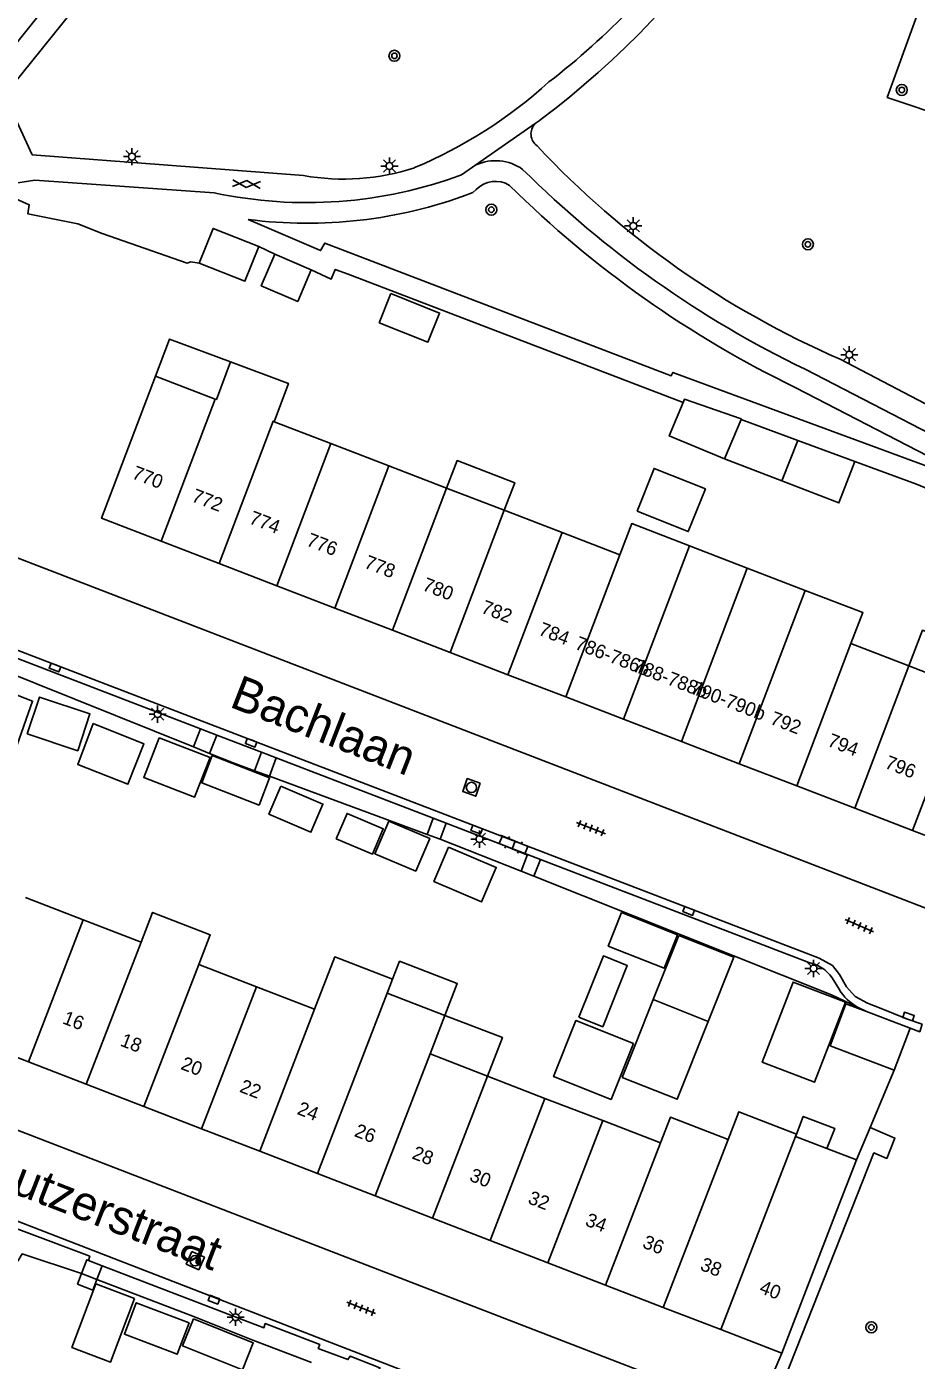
# Model space of a CAD drawing. Extents: x 132999 to 136000, y 398499 to 400501.
# Drawn here: x 134407.7 to 134472.4, y 398964.6 to 399061.5 of the extents above; entities that cross this region are included whole.
import ezdxf

# ---------------------------------------------------------------- set-up
doc = ezdxf.new("R2010")
doc.units = 0
for name, color, linetype in [('gg-afsc-erfafscheiding', 7, 'Continuous'), ('gg-afsc-muur', 7, 'Continuous'), ('gg-anno-huisnummerreeks BGT', 7, 'Continuous'), ('gg-anno-openbare ruimte label', 7, 'Continuous'), ('gg-bbg-bijgebouw', 7, 'Continuous'), ('gg-bbg-gedigitaliseerde bebouwing', 7, 'Continuous'), ('gg-bbg-gedigitaliseerde bijgebouw', 7, 'Continuous'), ('gg-bbg-hoofdgebouw', 7, 'Continuous'), ('gg-bbg-luifel en loopbrug', 7, 'Continuous'), ('gg-bbg-tussenscheiding', 7, 'Continuous'), ('gg-knt-verharding', 7, 'Continuous'), ('gt-grn-groengrens', 7, 'Continuous'), ('gt-grn-vlakafsluiter', 7, 'Continuous'), ('gt-grn-weggrens', 7, 'Continuous'), ('gt-symb-boom', 7, 'Continuous'), ('gt-symb-gesloten verharding', 7, 'Continuous'), ('gt-symb-klinker verharding', 7, 'Continuous'), ('gt-symb-kolk', 7, 'Continuous'), ('gt-symb-lichtmast', 7, 'Continuous'), ('gt-symb-rioolschacht', 7, 'Continuous'), ('gt-symb-tegel verharding', 7, 'Continuous')]:
    doc.layers.add(name, color=color, linetype=linetype)

# ---------------------------------------------------------------- blocks, each defined once
blk = doc.blocks.new('gt0-GESVH1')
at = {"layer": 'gt-symb-gesloten verharding'}
for p, q in [((-0.992, -0.261), (0.008, 0.239)), ((0.008, -0.261), (-0.992, 0.239)), ((0.008, 0.239), (1.008, -0.261)), ((1.008, 0.239), (0.008, -0.261))]:
    blk.add_line(p, q, dxfattribs=at)
blk = doc.blocks.new('gt0-LMAST')
at = {"layer": 'gt-symb-lichtmast'}
for p, q in [((-0.182, 0.173), (-0.447, 0.438)), ((-0.005, 0.246), (-0.005, 0.621)), ((0.172, 0.173), (0.437, 0.438)), ((-0.255, -0.004), (-0.63, -0.004)), ((-0.182, -0.181), (-0.447, -0.446)), ((-0.005, -0.254), (-0.005, -0.629)), ((0.437, -0.446), (0.172, -0.181)), ((0.245, -0.004), (0.62, -0.004))]:
    blk.add_line(p, q, dxfattribs=at)
blk.add_circle((-0.005, -0.004), 0.25, dxfattribs=at)
blk = doc.blocks.new('gt0-BOOM')
at = {"layer": 'gt-symb-boom'}
for radius in [0.4, 0.2]:
    blk.add_circle((0, 0), radius, dxfattribs=at)
blk = doc.blocks.new('gt0-KOLK')
at = {"layer": 'gt-symb-kolk'}
blk.add_lwpolyline([(0, 0), (0.375, 0), (0.375, 0.4), (-0.375, 0.4), (-0.375, 0), (0, 0)], dxfattribs=at)
blk = doc.blocks.new('gt0-RS')
at = {"layer": 'gt-symb-rioolschacht'}
blk.add_lwpolyline([(-0.5, -0.5), (0.5, -0.5), (0.5, 0.5), (-0.5, 0.5)], close=True, dxfattribs=at)
blk.add_circle((0, 0), 0.375, dxfattribs=at)
blk = doc.blocks.new('gt0-KL1')
at = {"layer": 'gt-symb-klinker verharding'}
for p, q in [((-1.15, 0.3), (1.15, 0.3)), ((-1, -0.3), (-1, 0.3)), ((-0.5, 0.3), (-0.5, 0.45)), ((0, -0.3), (0, 0.3)), ((0.5, 0.3), (0.5, 0.45)), ((1, -0.3), (1, 0.3)), ((-1.15, -0.3), (1.15, -0.3)), ((-0.5, -0.45), (-0.5, -0.3)), ((0.5, -0.45), (0.5, -0.3))]:
    blk.add_line(p, q, dxfattribs=at)
blk = doc.blocks.new('gt0-TEG1')
at = {"layer": 'gt-symb-tegel verharding'}
for p, q in [((-1.125, 0), (1.125, 0)), ((-0.9, -0.25), (-0.9, 0.25)), ((-0.45, -0.25), (-0.45, 0.25)), ((0, -0.25), (0, 0.25)), ((0.45, -0.25), (0.45, 0.25)), ((0.9, -0.25), (0.9, 0.25))]:
    blk.add_line(p, q, dxfattribs=at)

msp = doc.modelspace()

# ---------------------------------------------------------------- linework, layer by layer
at = {"layer": 'gg-afsc-erfafscheiding'}
for p, q in [((134406.46, 399023.137), (134411.423, 399021.222)), ((134419.832, 399009.154), (134404.31, 399015.39)), ((134420.998, 399008.686), (134419.832, 399009.154)), ((134425.36, 399007.022), (134424.287, 399007.417)), ((134436.83, 399002.796), (134425.36, 399007.022)), ((134437.775, 399002.448), (134436.83, 399002.796)), ((134437.775, 399002.448), (134443.657, 399000.128)), ((134443.657, 399000.128), (134444.587, 398999.757)), ((134469.032, 398981.481), (134470.799, 398985.653)), ((134468.038, 398979.133), (134469.032, 398981.481)), ((134411.704, 398970.859), (134412.134, 398970.689)), ((134412.134, 398970.689), (134412.827, 398970.424)), ((134412.827, 398970.424), (134419.924, 398967.716)), ((134462.61, 398965.08), (134460.7, 398960.57))]:
    msp.add_line(p, q, dxfattribs=at)
for points in [[(134467.921, 399029.91), (134472.408, 399028.252), (134490.606, 399020.656)], [(134424.287, 399007.417), (134422.718, 399007.995), (134420.998, 399008.686)], [(134444.587, 398999.757), (134466.239, 398991.129), (134468.124, 398990.227)]]:
    msp.add_lwpolyline(points, dxfattribs=at)
at = {"layer": 'gg-afsc-muur'}
msp.add_line((134424.597, 399045.554), (134425.751, 399044.979), dxfattribs=at)
for points in [[(134420.248, 399044.324), (134419.657, 399044.429), (134419.393, 399044.341), (134413.201, 399046.499), (134411.429, 399047.204), (134407.788, 399047.923), (134407.899, 399048.584), (134406.668, 399049.129)], [(134428.406, 399043.847), (134429.861, 399043.176), (134430.155, 399043.879), (134431.085, 399043.541), (134455.438, 399034.195)], [(134419.924, 398967.716), (134424.151, 398966.034), (134428.422, 398964.39)]]:
    msp.add_lwpolyline(points, dxfattribs=at)
at = {"layer": 'gg-bbg-bijgebouw'}
msp.add_line((134425.751, 399044.979), (134428.406, 399043.847), dxfattribs=at)
for points in [[(134420.248, 399044.324), (134421.267, 399046.861), (134424.597, 399045.554)], [(134424.597, 399045.554), (134423.578, 399043.018), (134420.248, 399044.324)], [(134428.406, 399043.847), (134427.429, 399041.557), (134424.774, 399042.689), (134425.751, 399044.979)], [(134455.438, 399034.195), (134455.542, 399034.444), (134459.669, 399033.004), (134459.653, 399032.965)], [(134458.463, 399030.101), (134454.433, 399031.775), (134455.438, 399034.195)]]:
    msp.add_lwpolyline(points, dxfattribs=at)
at = {"layer": 'gg-bbg-gedigitaliseerde bebouwing'}
for p, q in [((134455.897, 399023.783), (134460.109, 399022.163)), ((134460.109, 399022.163), (134464.318, 399020.543)), ((134407.624, 398998.21), (134411.83, 398996.584)), ((134411.83, 398996.584), (134416.028, 398994.961)), ((134420.225, 398993.338), (134424.422, 398991.716)), ((134424.422, 398991.716), (134428.646, 398990.083)), ((134434.312, 398992.26), (134433.924, 398991.257)), ((134438.122, 398989.635), (134433.924, 398991.257)), ((134437.041, 398986.837), (134438.122, 398989.635)), ((134437.041, 398986.837), (134441.22, 398985.222)), ((134441.22, 398985.222), (134445.399, 398983.606)), ((134445.399, 398983.606), (134449.597, 398981.983)), ((134449.597, 398981.983), (134453.794, 398980.361)), ((134463.617, 398980.841), (134463.681, 398981.006)), ((134465.902, 398979.958), (134463.617, 398980.841)), ((134468.038, 398979.133), (134465.902, 398979.958))]:
    msp.add_line(p, q, dxfattribs=at)
for points in [[(134450.837, 399023.135), (134451.707, 399025.395), (134455.897, 399023.783)], [(134464.318, 399020.543), (134468.517, 399018.928), (134467.647, 399016.667)], [(134420.225, 398993.338), (134421.06, 398995.503), (134416.864, 398997.124), (134416.028, 398994.961)], [(134428.646, 398990.083), (134430.115, 398993.883), (134434.312, 398992.26)], [(134458.714, 398980.612), (134454.516, 398982.233), (134453.794, 398980.361)], [(134458.714, 398980.612), (134459.491, 398982.625), (134463.681, 398981.006)]]:
    msp.add_lwpolyline(points, dxfattribs=at)
at = {"layer": 'gg-bbg-gedigitaliseerde bijgebouw'}
for p, q in [((134433.352, 399040.006), (134434.197, 399042.119)), ((134459.653, 399032.965), (134463.787, 399031.437)), ((134463.787, 399031.437), (134467.921, 399029.91)), ((134458.463, 399030.101), (134462.614, 399028.504)), ((134453.275, 398990.793), (134455.131, 398995.452)), ((134457.266, 398989.203), (134453.275, 398990.793)), ((134467.282, 398990.482), (134468.775, 398989.915)), ((134468.775, 398989.915), (134471.959, 398988.705)), ((134471.959, 398988.705), (134470.799, 398985.653))]:
    msp.add_line(p, q, dxfattribs=at)
for points in [[(134434.197, 399042.119), (134437.738, 399040.704), (134436.893, 399038.591), (134433.352, 399040.006)], [(134462.614, 399028.504), (134466.766, 399026.906), (134467.921, 399029.91)], [(134417.346, 399009.826), (134421.044, 399008.387), (134419.922, 399005.505), (134416.224, 399006.944), (134417.346, 399009.826)], [(134421.213, 399008.536), (134425.381, 399006.914), (134424.61, 399004.931), (134420.441, 399006.553), (134421.213, 399008.536)], [(134426.198, 399006.31), (134429.252, 399005.006), (134428.376, 399002.954), (134425.322, 399004.258), (134426.198, 399006.31)], [(134430.222, 399002.479), (134431.011, 399004.326), (134433.64, 399003.204), (134432.851, 399001.357), (134430.222, 399002.479)], [(134434.054, 399003.768), (134433.04, 399001.394), (134436.003, 399000.129), (134437.017, 399002.504), (134434.054, 399003.768)], [(134438.395, 399001.872), (134437.327, 398999.37), (134440.79, 398997.892), (134441.858, 399000.394), (134438.395, 399001.872)], [(134450.972, 398997.109), (134455.041, 398995.488), (134454.074, 398993.061), (134450.005, 398994.682), (134450.972, 398997.109)], [(134455.131, 398995.452), (134459.122, 398993.862), (134457.266, 398989.203)], [(134467.252, 398990.589), (134465.005, 398984.775), (134461.194, 398986.247), (134463.441, 398992.062), (134467.252, 398990.589)], [(134470.799, 398985.653), (134466.122, 398987.43), (134467.282, 398990.482)], [(134415.566, 398969.059), (134413.815, 398964.431), (134410.999, 398965.497), (134412.749, 398970.124), (134415.566, 398969.059)], [(134419.529, 398967.287), (134415.682, 398968.742), (134414.817, 398966.453), (134418.664, 398964.998), (134419.529, 398967.287)]]:
    msp.add_lwpolyline(points, dxfattribs=at)
at = {"layer": 'gg-bbg-hoofdgebouw'}
for p, q in [((134426.686, 399035.615), (134422.529, 399037.166)), ((134421.419, 399034.455), (134417.091, 399036.12)), ((134429.838, 399031.215), (134425.706, 399032.805)), ((134434.037, 399029.599), (134429.838, 399031.215)), ((134438.237, 399027.983), (134434.037, 399029.599)), ((134442.437, 399026.367), (134438.237, 399027.983)), ((134446.638, 399024.751), (134442.437, 399026.367)), ((134450.837, 399023.135), (134446.638, 399024.751)), ((134417.49, 399024.114), (134421.699, 399022.495)), ((134421.699, 399022.495), (134425.909, 399020.875)), ((134425.909, 399020.875), (134430.108, 399019.259)), ((134430.108, 399019.259), (134434.309, 399017.642)), ((134434.309, 399017.642), (134438.508, 399016.027)), ((134438.508, 399016.027), (134442.709, 399014.41)), ((134471.856, 399015.047), (134467.647, 399016.667)), ((134476.055, 399013.431), (134471.856, 399015.047)), ((134442.709, 399014.41), (134446.908, 399012.794)), ((134446.908, 399012.794), (134451.108, 399011.178)), ((134451.108, 399011.178), (134455.317, 399009.559)), ((134455.317, 399009.559), (134459.527, 399007.939)), ((134459.527, 399007.939), (134463.717, 399006.326)), ((134463.717, 399006.326), (134467.926, 399004.707)), ((134467.926, 399004.707), (134472.126, 399003.091)), ((134472.126, 399003.091), (134476.316, 399001.478)), ((134407.84, 398986.254), (134403.634, 398987.88)), ((134412.037, 398984.631), (134407.84, 398986.254)), ((134416.234, 398983.009), (134412.037, 398984.631)), ((134420.432, 398981.386), (134416.234, 398983.009)), ((134424.656, 398979.753), (134420.432, 398981.386)), ((134428.854, 398978.13), (134424.656, 398979.753)), ((134466.6, 398975.41), (134468.038, 398979.133)), ((134433.051, 398976.507), (134428.854, 398978.13)), ((134437.23, 398974.892), (134433.051, 398976.507)), ((134466.6, 398975.41), (134462.61, 398965.08)), ((134441.409, 398973.276), (134437.23, 398974.892)), ((134445.607, 398971.653), (134441.409, 398973.276)), ((134449.804, 398970.031), (134445.607, 398971.653)), ((134454.001, 398968.408), (134449.804, 398970.031)), ((134458.188, 398966.789), (134454.001, 398968.408)), ((134462.61, 398965.08), (134458.188, 398966.789))]:
    msp.add_line(p, q, dxfattribs=at)
for points in [[(134422.529, 399037.166), (134421.506, 399034.422), (134421.419, 399034.455)], [(134417.091, 399036.12), (134413.161, 399025.78), (134417.49, 399024.114)], [(134425.706, 399032.805), (134426.746, 399035.593), (134426.686, 399035.615)]]:
    msp.add_lwpolyline(points, dxfattribs=at)
at = {"layer": 'gg-bbg-luifel en loopbrug'}
for p, q in [((134453.275, 398990.793), (134451.979, 398987.541)), ((134451.979, 398987.541), (134451.018, 398985.129))]:
    msp.add_line(p, q, dxfattribs=at)
for points in [[(134422.529, 399037.166), (134418.098, 399038.819), (134417.091, 399036.12)], [(134438.237, 399027.983), (134439.006, 399029.982), (134443.206, 399028.366), (134442.437, 399026.367)], [(134452.09, 399026.305), (134453.33, 399029.408), (134457.058, 399027.917), (134455.818, 399024.815), (134452.09, 399026.305)], [(134471.856, 399015.047), (134472.852, 399017.637), (134477.052, 399016.021), (134476.055, 399013.431)], [(134402.644, 399010.99), (134407.019, 399009.3), (134408.148, 399012.495), (134403.844, 399014.158)], [(134407.748, 399010.104), (134411.422, 399008.884), (134412.313, 399011.566), (134408.639, 399012.786), (134407.748, 399010.104)], [(134412.556, 399010.851), (134411.433, 399007.891), (134415.072, 399006.442), (134416.243, 399009.382), (134412.556, 399010.851)], [(134447.872, 398989.503), (134449.649, 398993.962), (134451.382, 398993.272), (134449.605, 398988.812), (134447.872, 398989.503)], [(134434.312, 398992.26), (134434.822, 398993.578), (134439.019, 398991.956), (134438.122, 398989.635)], [(134438.122, 398989.635), (134442.301, 398988.021), (134441.22, 398985.222)], [(134451.835, 398987.598), (134450.211, 398983.523), (134446.03, 398985.189), (134447.654, 398989.264), (134451.835, 398987.598)], [(134451.018, 398985.129), (134455.009, 398983.538), (134457.266, 398989.203)], [(134463.681, 398981.006), (134464.179, 398982.297), (134466.465, 398981.414), (134465.902, 398979.958)], [(134419.835, 398967.572), (134424.19, 398965.839), (134423.407, 398963.871), (134419.053, 398965.604), (134419.835, 398967.572)]]:
    msp.add_lwpolyline(points, dxfattribs=at)
at = {"layer": 'gg-bbg-tussenscheiding'}
for p, q in [((134417.49, 399024.114), (134421.419, 399034.455)), ((134459.653, 399032.965), (134458.463, 399030.101)), ((134462.614, 399028.504), (134463.787, 399031.437)), ((134425.909, 399020.875), (134429.838, 399031.215)), ((134430.108, 399019.259), (134434.037, 399029.599)), ((134434.309, 399017.642), (134438.237, 399027.983)), ((134438.508, 399016.027), (134442.437, 399026.367)), ((134442.709, 399014.41), (134446.638, 399024.751)), ((134451.108, 399011.178), (134455.897, 399023.783)), ((134446.908, 399012.794), (134450.837, 399023.135)), ((134455.317, 399009.559), (134460.109, 399022.163)), ((134459.527, 399007.939), (134464.318, 399020.543)), ((134463.717, 399006.326), (134467.647, 399016.667)), ((134467.926, 399004.707), (134471.856, 399015.047)), ((134472.126, 399003.091), (134476.055, 399013.431)), ((134407.84, 398986.254), (134411.83, 398996.584)), ((134416.028, 398994.961), (134412.037, 398984.631)), ((134416.234, 398983.009), (134420.225, 398993.338)), ((134424.422, 398991.716), (134420.432, 398981.386)), ((134433.924, 398991.257), (134428.854, 398978.13)), ((134428.646, 398990.083), (134424.656, 398979.753)), ((134437.041, 398986.837), (134433.051, 398976.507)), ((134441.22, 398985.222), (134437.23, 398974.892)), ((134441.409, 398973.276), (134445.399, 398983.606)), ((134445.607, 398971.653), (134449.597, 398981.983)), ((134449.804, 398970.031), (134453.794, 398980.361)), ((134454.001, 398968.408), (134458.714, 398980.612)), ((134458.188, 398966.789), (134463.617, 398980.841))]:
    msp.add_line(p, q, dxfattribs=at)
msp.add_lwpolyline([(134421.699, 399022.495), (134425.629, 399032.835), (134425.706, 399032.805)], dxfattribs=at)
at = {"layer": 'gg-knt-verharding'}
for p, q in [((134405.871, 399056.24), (134416.639, 399069.675)), ((134445.037, 399054.728), (134444.68, 399054.479)), ((134408.111, 399052.203), (134427.845, 399050.705)), ((134439.329, 399050.75), (134440.376, 399051.48)), ((134408.297, 399050.372), (134406.611, 399050.09)), ((134408.297, 399050.372), (134421.345, 399049.453)), ((134483.304, 399028.718), (134466.849, 399037.36)), ((134411.423, 399021.222), (134478.85, 398995.21)), ((134404.227, 399016.668), (134420.361, 399010.47)), ((134420.361, 399010.47), (134419.832, 399009.154)), ((134420.361, 399010.47), (134421.534, 399010.019)), ((134421.534, 399010.019), (134420.998, 399008.686)), ((134421.534, 399010.019), (134424.785, 399008.77)), ((134424.785, 399008.77), (134424.287, 399007.417)), ((134424.785, 399008.77), (134425.853, 399008.36)), ((134425.853, 399008.36), (134425.36, 399007.022)), ((134425.853, 399008.36), (134437.265, 399003.976)), ((134437.265, 399003.976), (134436.83, 399002.796)), ((134437.265, 399003.976), (134438.205, 399003.614)), ((134438.205, 399003.614), (134437.775, 399002.448)), ((134438.205, 399003.614), (134444.138, 399001.335)), ((134444.138, 399001.335), (134443.657, 399000.128)), ((134444.138, 399001.335), (134445.073, 399000.976)), ((134445.073, 399000.976), (134444.587, 398999.757)), ((134445.073, 399000.976), (134464.574, 398993.484)), ((134466.271, 398992.365), (134466.785, 398991.532)), ((134468.124, 398990.227), (134468.775, 398989.915)), ((134393.287, 398986.615), (134460.7, 398960.57)), ((134447.001, 398959.21), (134384.341, 398983.45)), ((134412.21, 398971.819), (134413.213, 398971.435)), ((134413.213, 398971.435), (134412.827, 398970.424))]:
    msp.add_line(p, q, dxfattribs=at)
for points in [[(134403.469, 399056.423), (134404.841, 399057.7), (134414.015, 399069.143)], [(134408.111, 399052.203), (134406.871, 399054.89), (134405.871, 399056.24)], [(134464.311, 399036.615), (134479.027, 399029.021), (134491.724, 399023.421)], [(134404.551, 399017.15), (134465.33, 398993.81), (134466.3, 398993.27), (134466.81, 398992.62), (134467.33, 398991.72), (134467.96, 398991.02), (134468.86, 398990.53), (134469.713, 398990.179)], [(134472.819, 398988.99), (134471.762, 398989.362), (134469.713, 398990.179)], [(134471.959, 398988.705), (134472.647, 398988.442), (134472.819, 398988.99)], [(134460.7, 398960.57), (134461.633, 398960.21), (134469.311, 398979.632), (134470.247, 398979.243), (134470.836, 398980.717), (134469.032, 398981.481)], [(134402.386, 398974.946), (134402.801, 398974.77), (134403.114, 398975.577), (134412.299, 398972.122), (134412.21, 398971.819)], [(134411.704, 398970.859), (134412.093, 398971.864), (134412.21, 398971.819)], [(134413.213, 398971.435), (134424.968, 398966.929), (134425.066, 398967.228), (134429.022, 398965.703), (134428.914, 398965.423), (134431.075, 398964.616), (134431.231, 398964.87), (134433.399, 398964.017), (134432.798, 398962.539)]]:
    msp.add_lwpolyline(points, dxfattribs=at)
for centre, radius, start, end in [((134406.493, 399106.108), 64.23, 306.87618, 345.61238), ((134411.169, 399102.081), 56.375, 307.75254, 324.23319), ((134422.673, 399082.825), 34.212, 292.76446, 312.26816), ((134445.465, 399053.732), 1.084, 136.4313, 233.983), ((134493.169, 399098.16), 66.252, 223.14329, 246.5927), ((134441.791, 399048.332), 3.451, 54.9078, 114.20199), ((134430.748, 399066.891), 16.445, 259.8304, 288.29641), ((134497.483, 399105.235), 76.217, 225.19721, 244.20018), ((134428.106, 399081.034), 32.297, 257.91597, 290.33405), ((134464.077, 398990.884), 2.647, 34.02129, 79.17707), ((134470.06, 398993.553), 3.848, 211.67666, 239.79682), ((134451.83, 398981.107), 30.047, 304.22724, 341.4073), ((134450.498, 398980.402), 32.546, 304.54627, 334.39129)]:
    msp.add_arc(centre, radius, start, end, dxfattribs=at)
at = {"layer": 'gt-grn-groengrens'}
for points in [[(134470.275, 399056.37), (134476.059, 399072.362), (134518.741, 399058.066), (134512.957, 399042.074), (134470.275, 399056.37)], [(134439.85, 399049.343), (134440.165, 399049.46), (134440.4, 399049.699)], [(134423.829, 399047.509), (134429.08, 399045.243), (134429.396, 399045.794), (134454.568, 399036.136), (134454.705, 399036.392), (134472.957, 399029.648), (134489.784, 399022.624), (134489.788, 399022.635), (134478.38, 399027.667), (134463.64, 399035.273)]]:
    msp.add_lwpolyline(points, dxfattribs=at)
for centre, radius, start, end in [((134441.792, 399048.332), 1.951, 58.12974, 135.52596), ((134497.489, 399105.24), 77.725, 225.30466, 244.18325), ((134428.105, 399081.046), 33.808, 262.7333, 290.32769)]:
    msp.add_arc(centre, radius, start, end, dxfattribs=at)
at = {"layer": 'gt-grn-vlakafsluiter'}
for points in [[(134411.704, 398970.859), (134407.382, 398972.297), (134407.063, 398971.764)], [(134411.704, 398970.859), (134411.412, 398970.097), (134412.536, 398969.666), (134412.827, 398970.424)]]:
    msp.add_lwpolyline(points, dxfattribs=at)
at = {"layer": 'gt-grn-weggrens'}
msp.add_line((134444.68, 399054.479), (134440.376, 399051.48), dxfattribs=at)

# ---------------------------------------------------------------- block references
at = {"layer": 'gt-symb-boom'}
for p in [(134434.452, 399059.411), (134471.343, 399056.929), (134441.501, 399048.223), (134464.516, 399045.706)]:
    msp.add_blockref('gt0-BOOM', p, dxfattribs=at)
at = {"layer": 'gt-symb-boom', "rotation": 158.90078775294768}
msp.add_blockref('gt0-BOOM', (134469.125, 398966.959), dxfattribs=at)
at = {"layer": 'gt-symb-gesloten verharding', "rotation": -3.6692540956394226}
msp.add_blockref('gt0-GESVH1', (134423.69, 399050.097), dxfattribs=at)
at = {"layer": 'gt-symb-klinker verharding', "rotation": -22.205643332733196}
msp.add_blockref('gt0-KL1', (134443.119, 399002.03), dxfattribs=at)
at = {"layer": 'gt-symb-kolk'}
for p, rotation in [((134409.837, 399015.12), 158.82666847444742), ((134424.106, 399009.639), 159.02828943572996), ((134440.5, 399003.34), 160.00710602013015), ((134455.928, 398997.42), 158.77323173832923), ((134471.762, 398989.362), -18.96025108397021), ((134421.397, 398969.155), 158.77323173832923)]:
    msp.add_blockref('gt0-KOLK', p, dxfattribs=dict(at, rotation=rotation))
at = {"layer": 'gt-symb-lichtmast'}
for p in [(134415.373, 399052.085), (134434.096, 399051.397), (134451.822, 399047.047), (134467.53, 399037.679), (134417.241, 399011.546), (134440.643, 399002.456), (134464.93, 398993.051), (134422.912, 398967.696)]:
    msp.add_blockref('gt0-LMAST', p, dxfattribs=at)
at = {"layer": 'gt-symb-rioolschacht'}
for p, rotation in [((134440.055, 399006.213), 160.4964267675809), ((134419.973, 398971.8), -114.25908445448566)]:
    msp.add_blockref('gt0-RS', p, dxfattribs=dict(at, rotation=rotation))
at = {"layer": 'gt-symb-tegel verharding'}
for p, rotation in [((134448.745, 399003.253), 158.90078774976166), ((134468.264, 398996.16), -24.003190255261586), ((134432.038, 398968.366), -21.58865227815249)]:
    msp.add_blockref('gt0-TEG1', p, dxfattribs=dict(at, rotation=rotation))

# ---------------------------------------------------------------- texts
at = {"layer": 'gg-anno-huisnummerreeks BGT'}
for s, rotation, p in [('770', 339, (134415.304, 399028.704)), ('772', 339, (134419.637, 399027.037)), ('774', 339, (134423.816, 399025.43)), ('776', 339, (134427.987, 399023.824)), ('778', 339, (134432.187, 399022.208)), ('780', 339, (134436.42, 399020.579)), ('782', 339, (134440.685, 399018.938)), ('784', 339, (134444.855, 399017.333)), ('786-786b', 339, (134447.508, 399016.31)), ('788-788b', 339, (134451.714, 399014.693)), ('790-790b', 339, (134455.923, 399013.073)), ('792', 339, (134461.699, 399010.852)), ('794', 339, (134465.867, 399009.248)), ('796', 339, (134470.037, 399007.644)), ('16', 338.8, (134410.256, 398989.074)), ('18', 338.9, (134414.452, 398987.45)), ('20', 338.8, (134418.855, 398985.75)), ('22', 338.8, (134423.13, 398984.097)), ('24', 338.8, (134427.311, 398982.481)), ('26', 338.8, (134431.474, 398980.871)), ('28', 338.9, (134435.662, 398979.251)), ('30', 338.8, (134439.841, 398977.636)), ('32', 338.8, (134444.094, 398975.992)), ('34', 338.9, (134448.26, 398974.38)), ('36', 338.8, (134452.424, 398972.772)), ('38', 338.8, (134456.616, 398971.151)), ('40', 338.9, (134460.92, 398969.486))]:
    msp.add_text(s, height=1, rotation=rotation, dxfattribs=at).set_placement(p)
at = {"layer": 'gg-anno-openbare ruimte label'}
for s, rotation, p in [('Bachlaan', 338.7, (134422.376, 399012.103)), ('Kreutzerstraat', 338.8, (134401.685, 398978.651))]:
    msp.add_text(s, height=2.5, rotation=rotation, dxfattribs=at).set_placement(p)

doc.saveas('drawing.dxf')
